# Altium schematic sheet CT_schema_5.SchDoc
size 522 x 390 mm
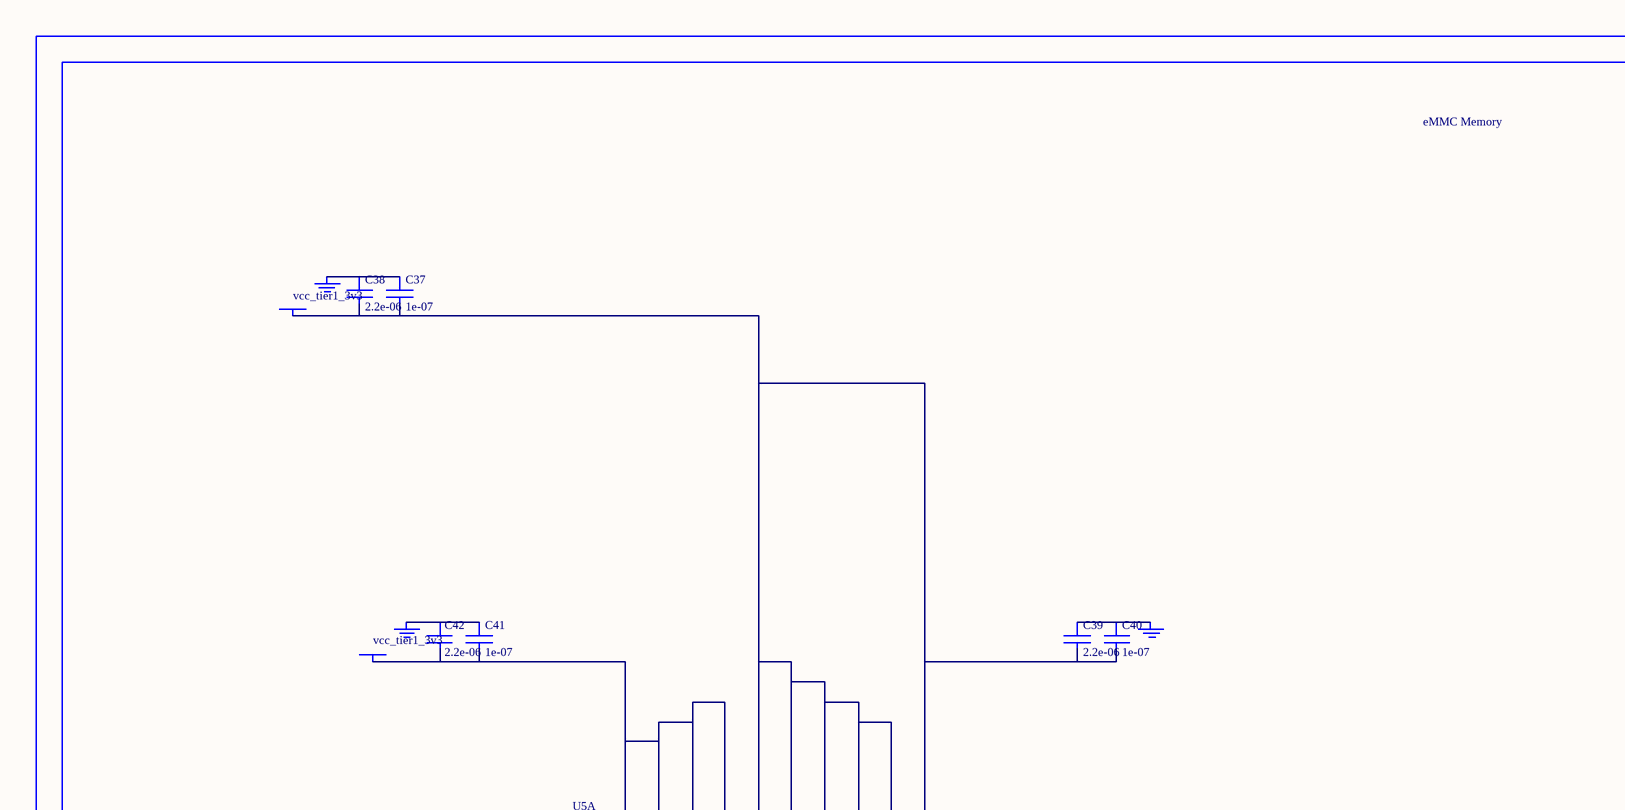
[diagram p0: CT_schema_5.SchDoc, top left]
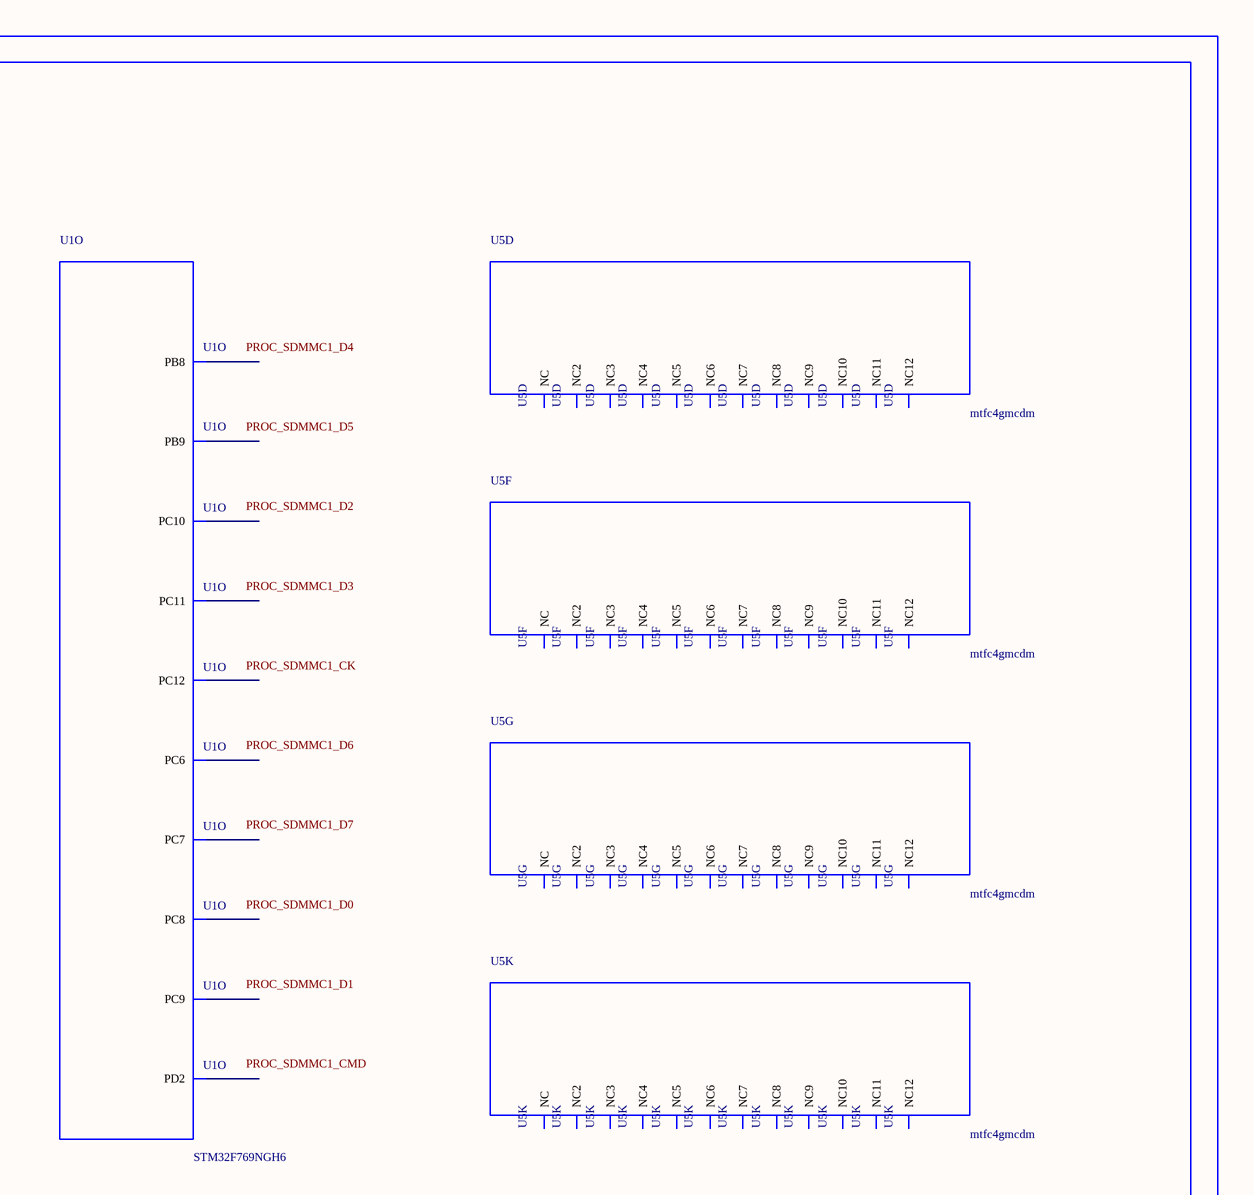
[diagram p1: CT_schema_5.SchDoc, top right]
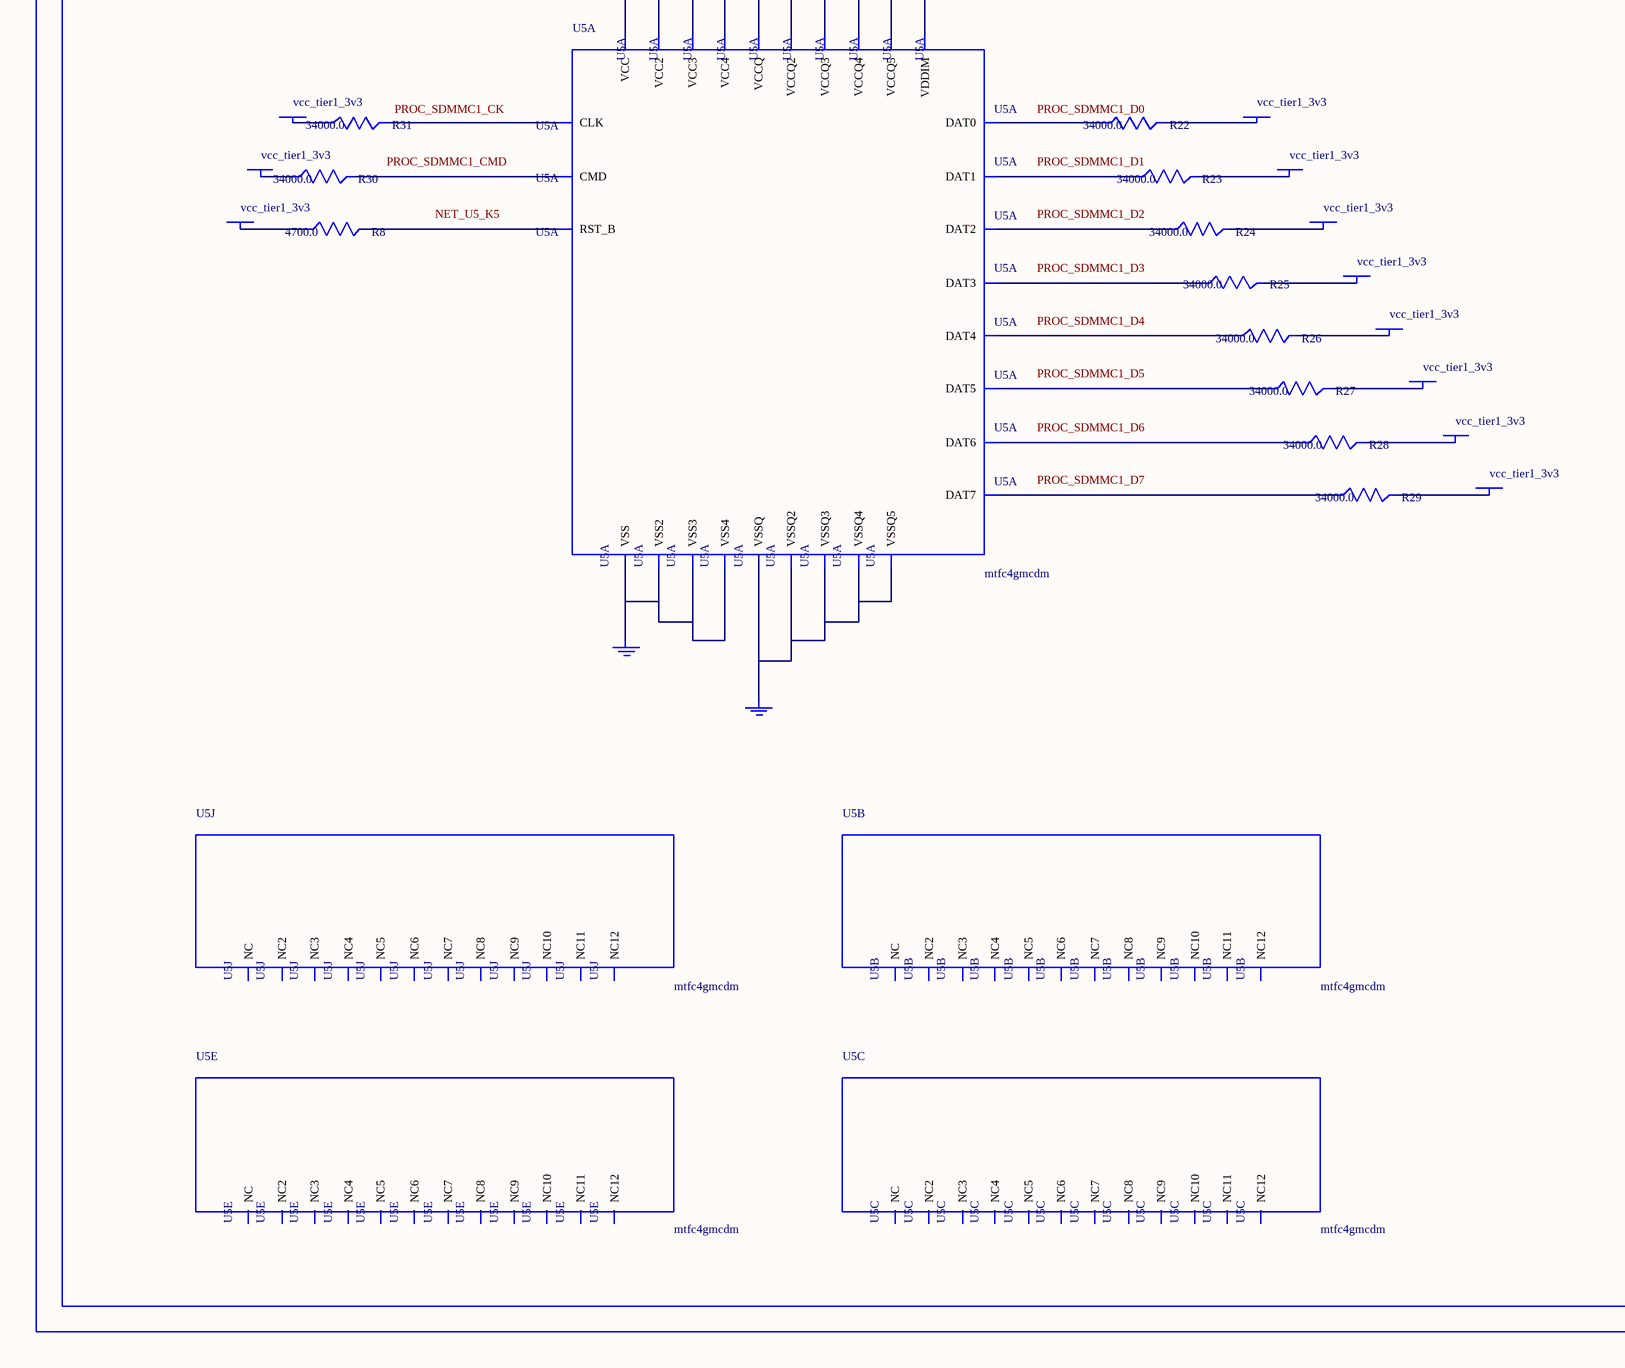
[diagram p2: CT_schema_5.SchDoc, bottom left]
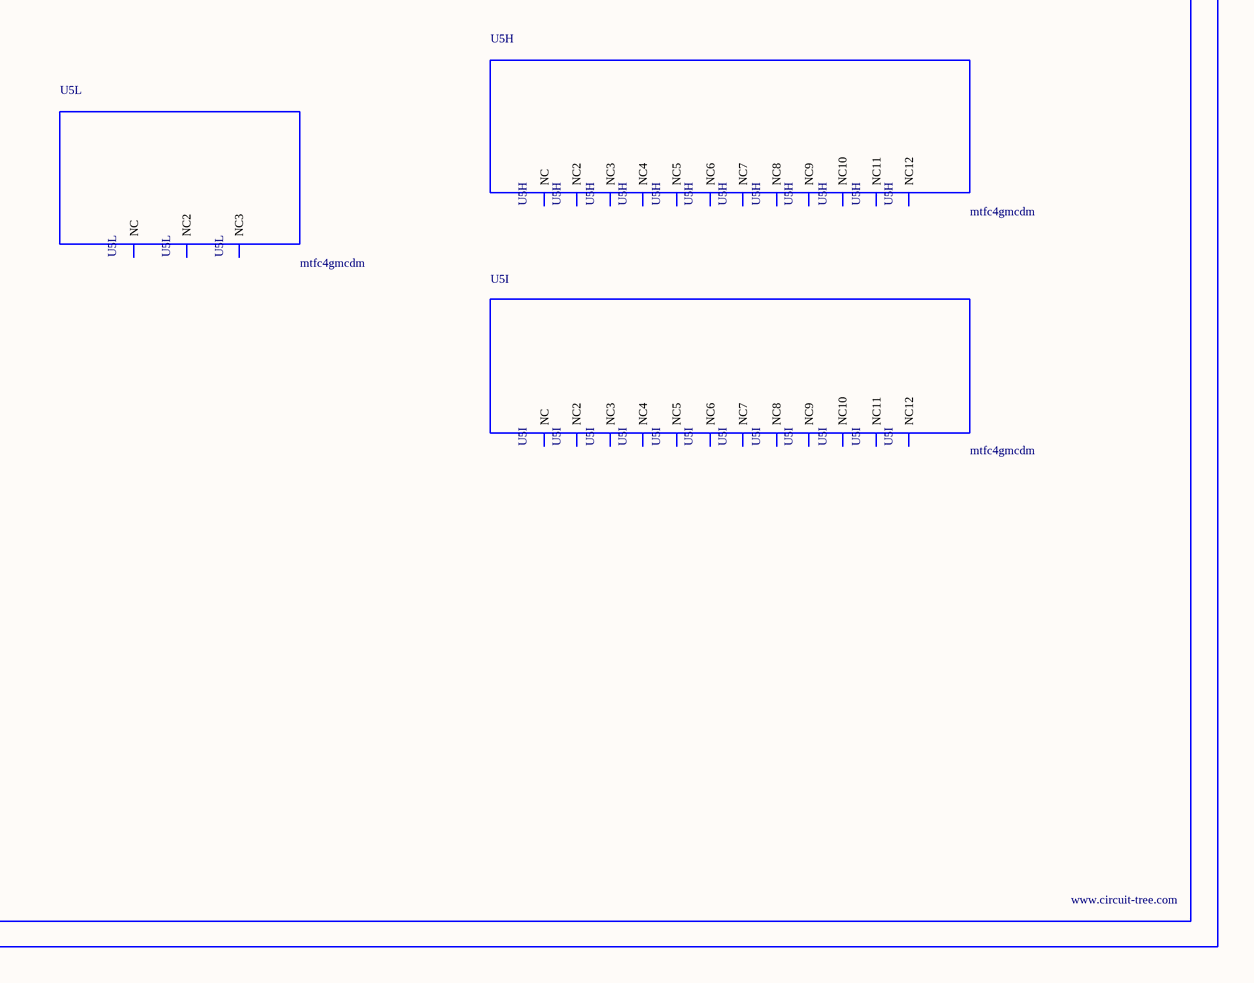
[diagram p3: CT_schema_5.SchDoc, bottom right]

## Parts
BORDER4  (no value)
C37  1e-07  [C0402]
C38  2.2e-06  [C0603]
C39  2.2e-06  [C0603]
C40  1e-07  [C0402]
C41  1e-07  [C0402]
C42  2.2e-06  [C0603]
GND_INSTANCE_4_0  (no value)
GND_INSTANCE_4_1  (no value)
GND_INSTANCE_4_2  (no value)
GND_INSTANCE_4_3  (no value)
GND_INSTANCE_4_4  (no value)
POWER_INSTANCE_4_0  vcc_tier1_3v3
POWER_INSTANCE_4_1  vcc_tier1_3v3
POWER_INSTANCE_4_2  vcc_tier1_3v3
POWER_INSTANCE_4_3  vcc_tier1_3v3
POWER_INSTANCE_4_4  vcc_tier1_3v3
POWER_INSTANCE_4_5  vcc_tier1_3v3
POWER_INSTANCE_4_6  vcc_tier1_3v3
POWER_INSTANCE_4_7  vcc_tier1_3v3
POWER_INSTANCE_4_8  vcc_tier1_3v3
POWER_INSTANCE_4_9  vcc_tier1_3v3
POWER_INSTANCE_4_10  vcc_tier1_3v3
POWER_INSTANCE_4_11  vcc_tier1_3v3
POWER_INSTANCE_4_12  vcc_tier1_3v3
R8  4700.0  [R0603]
R22  34000.0  [R0603]
R23  34000.0  [R0603]
R24  34000.0  [R0603]
R25  34000.0  [R0603]
R26  34000.0  [R0603]
R27  34000.0  [R0603]
R28  34000.0  [R0603]
R29  34000.0  [R0603]
R30  34000.0  [R0603]
R31  34000.0  [R0603]
U1  STM32F769NGH6  [TFBGA216]  (part O of 17)
U5  mtfc4gmcdm  [TFBGA-153]  (parts A,B,C,D,E,F,G,H,I,J,K,L of 12)

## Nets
NetC37_1: C37.1 C38.1 GND_INSTANCE_4_0.0(GND)
NetC37_2: C37.2 C38.2 C39.2 C40.2 POWER_INSTANCE_4_0.0(PWR) U5.C2(VDDIM) U5.C6(VCCQ) U5.M4(VCCQ2) U5.N4(VCCQ3) U5.P3(VCCQ4) U5.P5(VCCQ5)
NetC39_1: C39.1 C40.1 GND_INSTANCE_4_1.0(GND)
NetC41_1: C41.1 C42.1 GND_INSTANCE_4_2.0(GND)
NetC41_2: C41.2 C42.2 POWER_INSTANCE_4_1.0(PWR) U5.E6(VCC) U5.F5(VCC2) U5.J10(VCC3) U5.K9(VCC4)
NetGND_INSTANCE_4_3_0: GND_INSTANCE_4_3.0(GND) U5.E7(VSS) U5.G5(VSS2) U5.H10(VSS3) U5.K8(VSS4)
NetGND_INSTANCE_4_4_0: GND_INSTANCE_4_4.0(GND) U5.C4(VSSQ) U5.N2(VSSQ2) U5.N5(VSSQ3) U5.P4(VSSQ4) U5.P6(VSSQ5)
NetPOWER_INSTANCE_4_2_0: POWER_INSTANCE_4_2.0(PWR) R22.2
NetPOWER_INSTANCE_4_3_0: POWER_INSTANCE_4_3.0(PWR) R23.2
NetPOWER_INSTANCE_4_4_0: POWER_INSTANCE_4_4.0(PWR) R24.2
NetPOWER_INSTANCE_4_5_0: POWER_INSTANCE_4_5.0(PWR) R25.2
NetPOWER_INSTANCE_4_6_0: POWER_INSTANCE_4_6.0(PWR) R26.2
NetPOWER_INSTANCE_4_7_0: POWER_INSTANCE_4_7.0(PWR) R27.2
NetPOWER_INSTANCE_4_8_0: POWER_INSTANCE_4_8.0(PWR) R28.2
NetPOWER_INSTANCE_4_9_0: POWER_INSTANCE_4_9.0(PWR) R29.2
NetPOWER_INSTANCE_4_10_0: POWER_INSTANCE_4_10.0(PWR) R30.1
NetPOWER_INSTANCE_4_11_0: POWER_INSTANCE_4_11.0(PWR) R31.1
NetPOWER_INSTANCE_4_12_0: POWER_INSTANCE_4_12.0(PWR) R8.1
NetR8_2: R8.2 U5.K5(RST_B)
NetR22_1: R22.1 U5.A3(DAT0)
NetR23_1: R23.1 U5.A4(DAT1)
NetR24_1: R24.1 U5.A5(DAT2)
NetR25_1: R25.1 U5.B2(DAT3)
NetR26_1: R26.1 U5.B3(DAT4)
NetR27_1: R27.1 U5.B4(DAT5)
NetR28_1: R28.1 U5.B5(DAT6)
NetR29_1: R29.1 U5.B6(DAT7)
NetR30_2: R30.2 U5.M5(CMD)
NetR31_2: R31.2 U5.M6(CLK)

Not connected (* = marked no-connect by the designer): U1 A7(PB8) A12(PC12) B4(PB9) B13(PC11) B14(PC10) D12(PD2) F14(PC9) G14(PC8) G15(PC7) H15(PC6); U5 A1(NC) A2(NC7) A6(NC8) A7(NC9) A8(NC10) A9(NC11) A10(NC2) A11(NC3) A12(NC4) A13(NC5) A14(NC6) B1(NC12) B7(NC6) B8(NC7) B9(NC8) B10(NC) B11(NC2) B12(NC3) B13(NC4) B14(NC5) C1(NC9) C3(NC10) C5(NC11) C7(NC12) C8(NC6) C9(NC7) C10(NC) C11(NC2) C12(NC3) C13(NC4) C14(NC5) D1(NC8) D2(NC10) D3(NC11) D4(NC12) D12(NC9) D13(NC) D14(NC2) E1(NC3) E2(NC8) E3(NC9) E5(NC10) E8(NC11) E9(NC12) E10(NC4) E12(NC5) E13(NC6) E14(NC7) F1(NC) F2(NC6) F3(NC7) F10(NC2) F12(NC3) F13(NC4) F14(NC5) G1(NC8) G2(NC11) G3(NC12) G10(NC9) G12(NC10) G13(NC) G14(NC2) H1(NC3) H2(NC7) H3(NC8) H5(NC9) H12(NC4) H13(NC5) H14(NC6) J1(NC10) J2(NC11) J3(NC12) J5(NC4) J12(NC) J13(NC2) J14(NC3) K1(NC5) K2(NC9) K3(NC10) K6(NC11) K7(NC12) K10(NC6) K12(NC7) K13(NC8) K14(NC) L1(NC2) L2(NC6) L3(NC7) L12(NC3) L13(NC4) L14(NC5) M1(NC8) M2(NC9) M3(NC10) M7(NC11) M8(NC12) M9(NC6) M10(NC) M11(NC2) M12(NC3) M13(NC4) M14(NC5) N1(NC7) N3(NC8) N6(NC9) N7(NC10) N8(NC11) N9(NC12) N10(NC) N11(NC2) N12(NC3) N13(NC4) N14(NC5) P1(NC6) P2(NC9) P7(NC10) P8(NC11) P9(NC12) P10(NC7) P11(NC8) P12(NC) P13(NC2) P14(NC3)

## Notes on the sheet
- Labels drawn without touching a wire or pin: NET_U5_K5, PROC_SDMMC1_CK, PROC_SDMMC1_CMD, PROC_SDMMC1_D0, PROC_SDMMC1_D1, PROC_SDMMC1_D2, PROC_SDMMC1_D3, PROC_SDMMC1_D4, PROC_SDMMC1_D5, PROC_SDMMC1_D6, PROC_SDMMC1_D7

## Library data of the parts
BORDER4 = BORDER_PAGE4
C37 C40 C41 = C0402C104K3RACTU
C38 C39 C42 = C0603C225K8RACTU
GND_INSTANCE_4_0-GND_INSTANCE_4_4 = GND
POWER_INSTANCE_4_0-POWER_INSTANCE_4_12 = PWR
R8 = RC0603JR-074K7L
R22-R31 = ERA3ARB3402V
